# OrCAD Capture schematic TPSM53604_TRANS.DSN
size C; title: TPSM53604 36-V Input, 4-A Power Module in Enhanced; rev: 1.0; note: Datasheet: SNVSBC9B      EVM:SNVU627B; note: Synchronous Step Down Converter; note: HotRod™ QFN Package
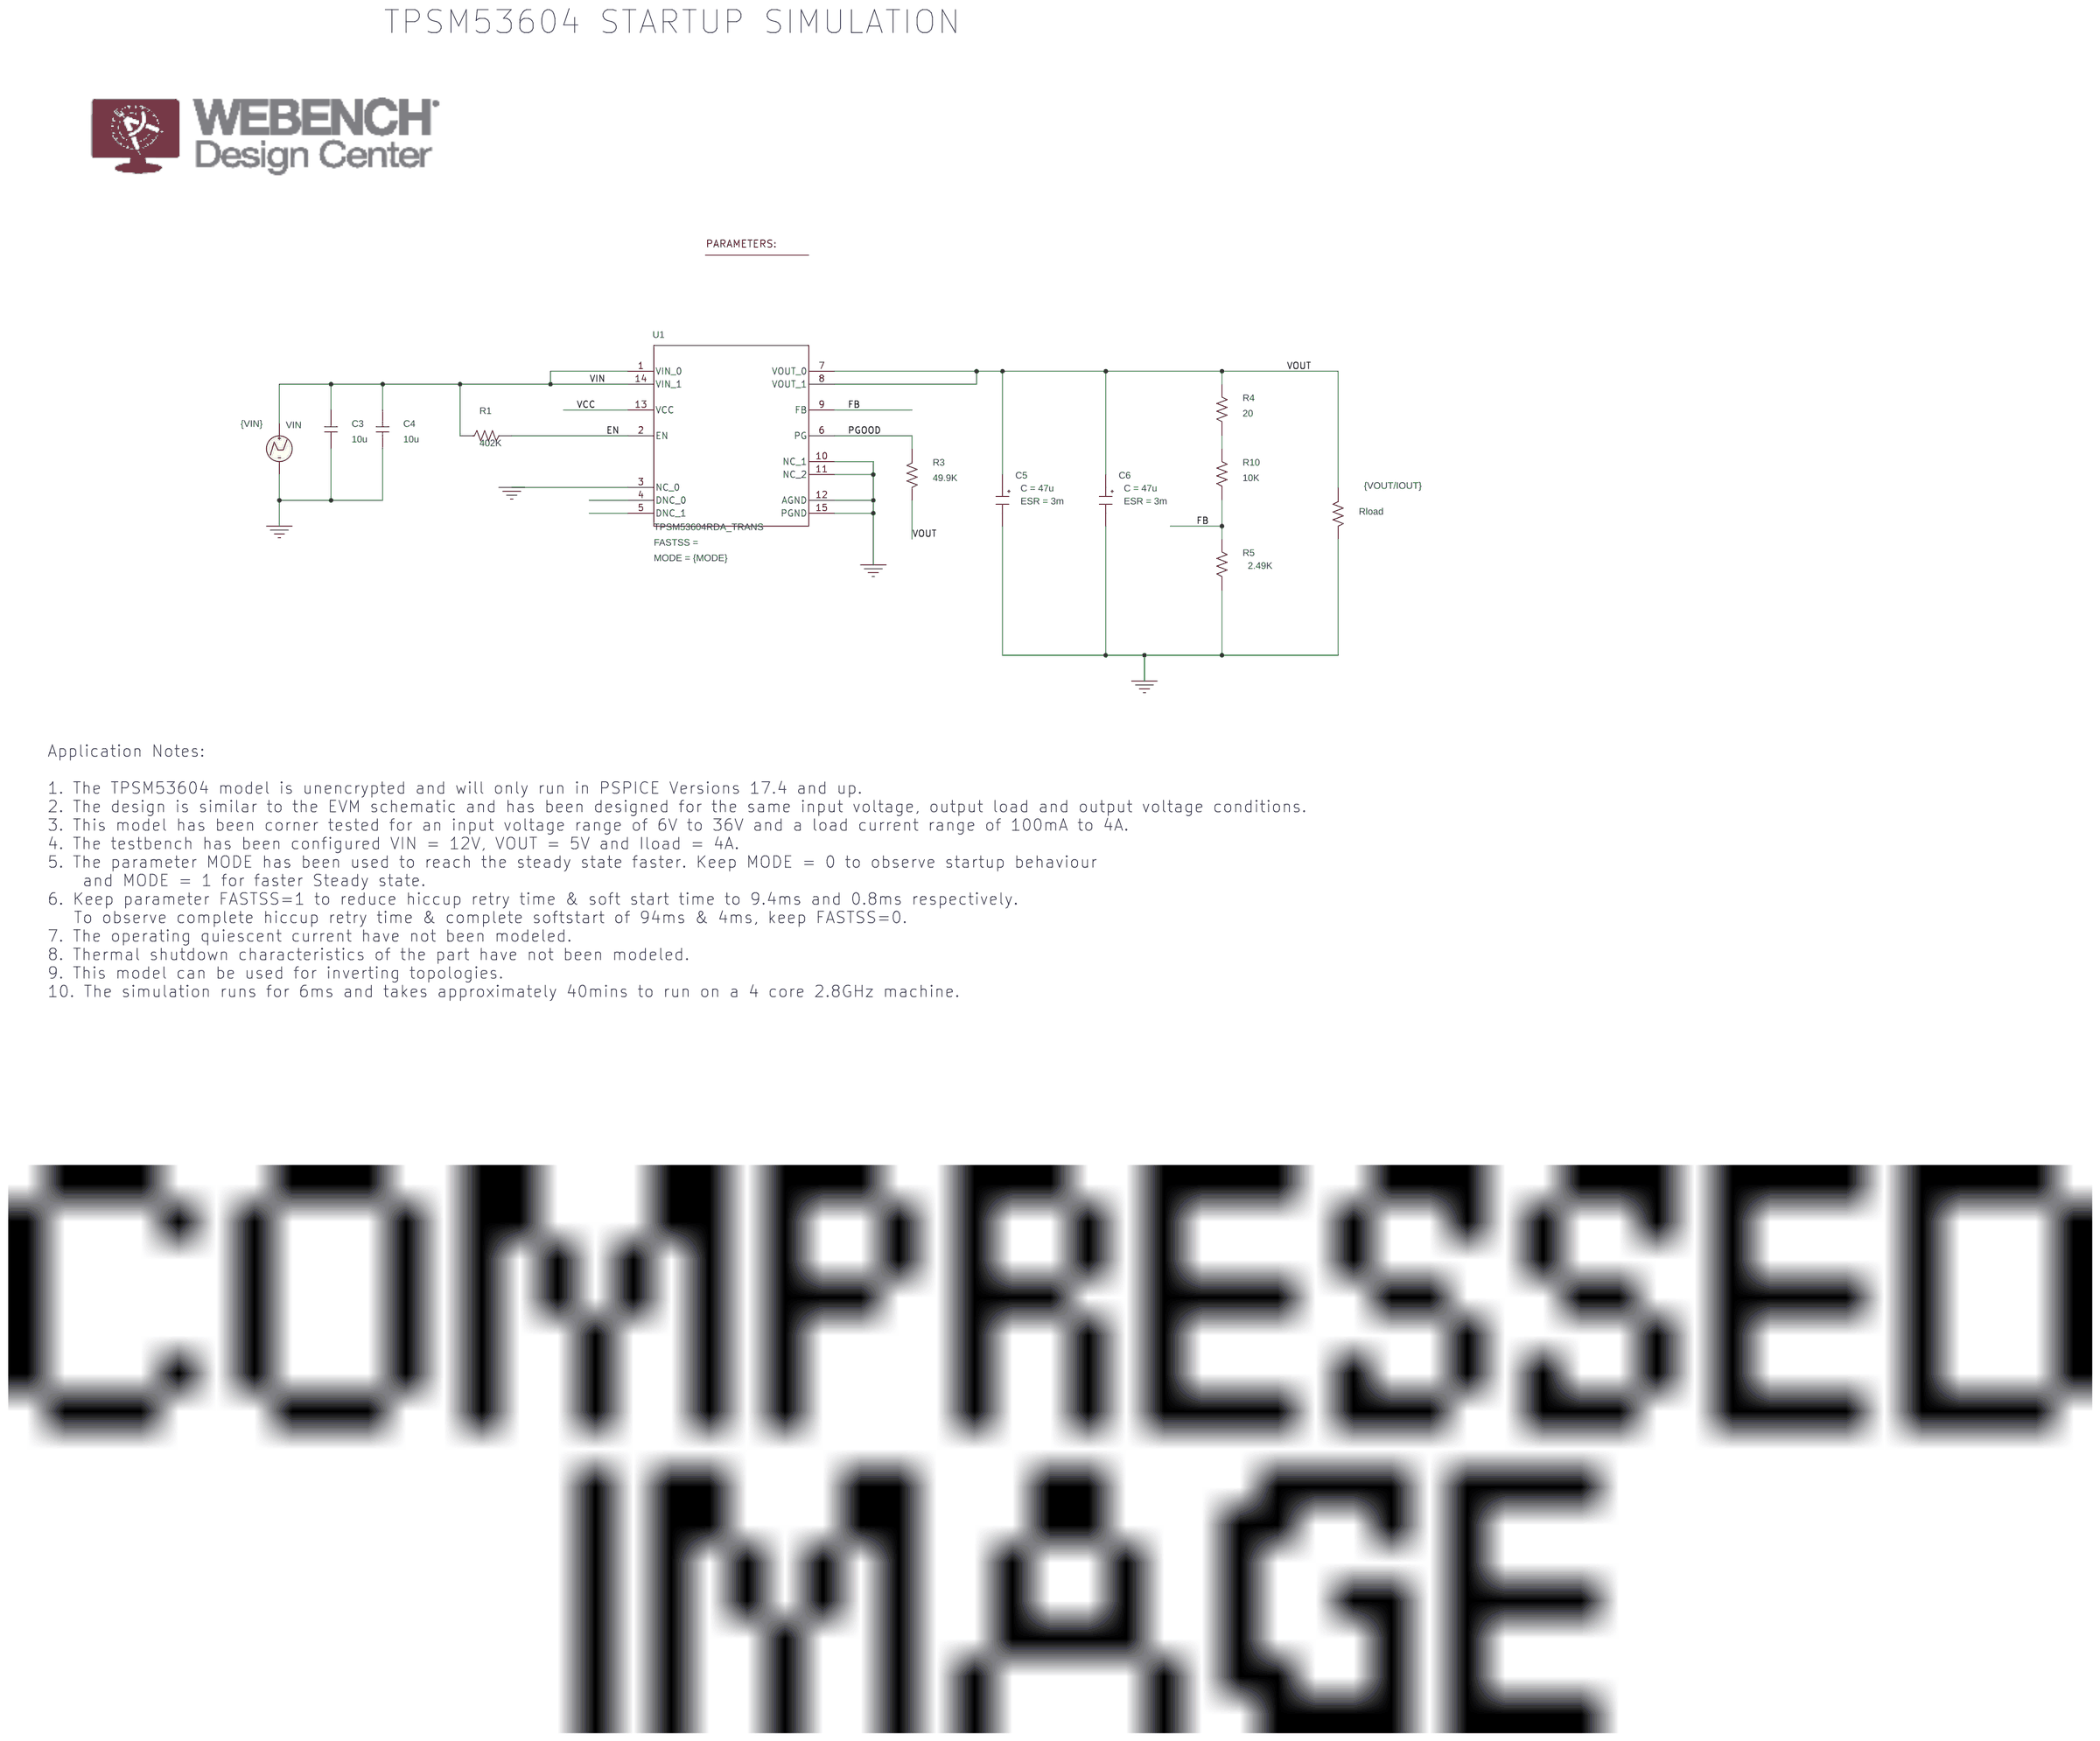
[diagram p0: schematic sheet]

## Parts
1  PARAM
C3  10u  [RAD/CK05]
C4  10u  [RAD/CK05]
C5  CESR
C6  CESR
R1  402K  [AX/RC05]
R3  49.9K  [AX/RC05]
R4  20  [AX/RC05]
R5  2.49K  [AX/RC05]
R10  10K  [AX/RC05]
Rload  {VOUT/IOUT}  [AX/RC05]
U1  TPSM53604RDA_TRANS  [RDA0015A]
VIN  VPWL

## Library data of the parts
1 = PARAM: FASTSS: 0; IOUT: 4; MODE: 0; VIN: 12; VOUT: 5
C3 C4 = C
C5 C6 = CESR_0: C: 47u; ESR: 3m; PSpiceTemplate: X^@REFDES %IN %OUT @MODEL PARAMS:  ?C|C=@C||C=100u|  ?ESR|ESR=@ESR||ESR=0.01| ?X|X=@X||X=2|  ?IC|IC=@IC||IC=2|; X: 1
R1 R3-R5 R10 Rload = R
U1 = TPSM53604RDA_TRANS: MODE: {MODE}
VIN = VPWL: PSpiceTemplate: V^@REFDES %+ %- ?DC|DC @DC| ?AC|AC @AC|\n+PWL @T1 @V1 @T2 @V2 #T3/@T3 @V3/ #T4/@T4 @V4/ #T5/@T5 @V5/ #T6/@T6 @V6/ #T7/@T7 @V7/ #T8/@T8 @V8/ #T9/@T9 @V9/ #T10/@T10 @V10/; T1: 0; T2: 10u; T3: 15m; V1: 0; V2: {VIN}; V3: {VIN}

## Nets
VCC: U1.13(VCC)
VIN: C3.2 C4.2 R1.1 U1.1(VIN_0) U1.14(VIN_1) VIN.1(+)
0: C3.1 C4.1 C5.2(OUT) C6.2(OUT) R5.1 Rload.2 U1.3(NC_0) U1.10(NC_1) U1.11(NC_2) U1.12(AGND) U1.15(PGND) VIN.2(-)
EN: R1.2 U1.2(EN)
FB: R5.2 R10.1 U1.9(FB)
PGOOD: R3.1 U1.6(PG)
VOUT: C5.1(IN) C6.1(IN) R3.2 R4.2 Rload.1 U1.7(VOUT_0) U1.8(VOUT_1)
N16775763: R4.1 R10.2

Not connected (* = marked no-connect by the designer): U1 4(DNC_0) 5(DNC_1)

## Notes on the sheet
- TPSM53604 STARTUP SIMULATION
- Application Notes:
  1. The TPSM53604 model is unencrypted and will only run in PSPICE Versions 17.4 and up.
  2. The design is similar to the EVM schematic and has been designed for the same input voltage, output load and output voltage conditions.
  3. This model has been corner tested for an input voltage range of 6V to 36V and a load current range of 100mA to 4A.
  4. The testbench has been configured VIN = 12V, VOUT = 5V and Iload = 4A.
  5. The parameter MODE has been used to reach the steady state faster. Keep MODE = 0 to observe startup behaviour
      and MODE = 1 for faster Steady state.
  6. Keep parameter FASTSS=1 to reduce hiccup retry time & soft start time to 9.4ms and 0.8ms respectively.
     To observe complete hiccup retry time & complete softstart of 94ms & 4ms, keep FASTSS=0.
  7. The operating quiescent current have not been modeled.
  8. Thermal shutdown characteristics of the part have not been modeled.
  9. This model can be used for inverting topologies.
  10. The simulation runs for 6ms and takes approximately 40mins to run on a 4 core 2.8GHz machine.
